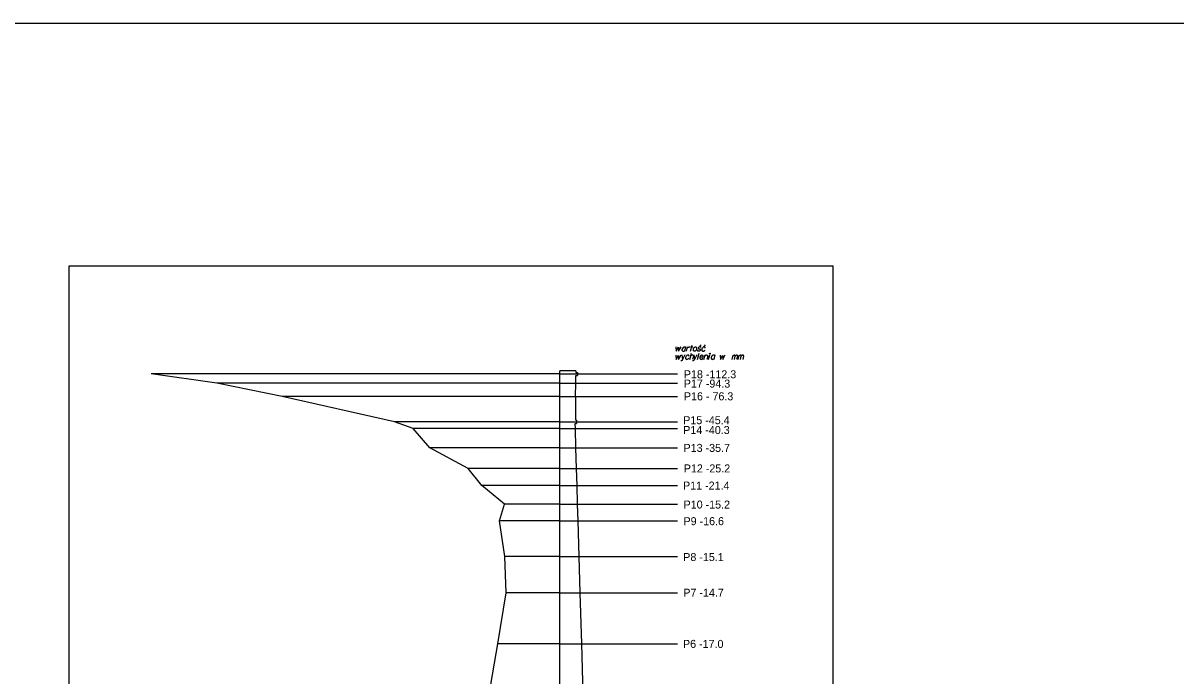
# Model space of a CAD drawing. Extents: x 138 to 6653, y -177 to 1520.
# Drawn here: x 195.15 to 226.83, y 20.71 to 38.66 of the extents above; entities that cross this region are included whole.
import ezdxf

# ---------------------------------------------------------------- set-up
doc = ezdxf.new("R2010")
doc.units = 0
for name, color, linetype in [('15 listopad 2008', 7, 'Continuous'), ('Ramka do drukowania', 7, 'Continuous'), ('Standart wykresów', 7, 'Continuous'), ('Wykresy 4 maj 2008', 7, 'Continuous')]:
    doc.layers.add(name, color=color, linetype=linetype)

msp = doc.modelspace()

# ---------------------------------------------------------------- linework, layer by layer
at = {"layer": '15 listopad 2008'}
msp.add_lwpolyline([(137.936, 38.661), (264.389, 38.661), (264.389, -75.347), (137.936, -75.347)], close=True, dxfattribs=at)
msp.add_lwpolyline([(209.897, 13.297), (209.107, 14.742), (208.657, 16.118), (208.377, 17.485), (208.277, 18.843), (207.957, 20.202), (208.197, 21.593), (208.427, 22.995), (208.387, 23.989), (208.237, 24.969), (208.377, 25.428), (207.757, 25.945), (207.377, 26.413), (206.327, 26.981), (205.867, 27.507), (205.357, 27.694), (202.267, 28.392), (200.467, 28.755), (198.667, 29.011)], dxfattribs=at)
at = {"layer": 'Ramka do drukowania'}
for p, q in [((196.41, 2.285), (196.41, 31.985)), ((196.41, 31.985), (217.41, 31.985)), ((217.41, 2.285), (217.41, 31.985))]:
    msp.add_line(p, q, dxfattribs=at)
at = {"layer": 'Standart wykresów'}
for p, q in [((210.343, 29.095), (209.897, 29.095)), ((209.897, 9.011), (209.897, 29.095)), ((209.897, 29.011), (213.134, 29.011)), ((210.343, 29.095), (210.343, 29.053)), ((210.343, 29.053), (210.38, 29.053)), ((210.343, 28.969), (210.38, 28.969)), ((210.343, 28.755), (210.343, 28.969)), ((210.38, 29.053), (210.38, 29.011)), ((210.38, 29.011), (210.38, 28.969)), ((209.897, 28.755), (213.134, 28.755)), ((210.328, 28.392), (210.343, 28.755)), ((209.897, 28.392), (213.134, 28.392)), ((210.328, 28.392), (210.328, 27.738)), ((209.897, 27.694), (213.134, 27.694)), ((210.328, 27.507), (210.324, 27.65)), ((210.324, 27.65), (210.358, 27.65)), ((210.358, 27.738), (210.328, 27.738)), ((210.358, 27.738), (210.358, 27.694)), ((210.358, 27.694), (210.358, 27.65)), ((209.897, 27.507), (213.134, 27.507)), ((210.343, 26.981), (210.328, 27.507)), ((209.897, 26.981), (213.134, 26.981)), ((210.358, 26.413), (210.343, 26.981)), ((209.897, 26.413), (213.134, 26.413)), ((210.373, 25.945), (210.358, 26.413)), ((209.897, 25.945), (213.134, 25.945)), ((210.385, 25.428), (210.373, 25.945)), ((209.897, 25.428), (213.134, 25.428)), ((210.402, 24.969), (210.385, 25.428)), ((209.897, 24.969), (213.134, 24.969)), ((210.43, 23.989), (210.402, 24.969)), ((209.897, 23.989), (213.134, 23.989)), ((210.46, 22.995), (210.43, 23.989)), ((209.897, 22.995), (213.134, 22.995)), ((210.5, 21.593), (210.46, 22.995)), ((209.897, 21.593), (213.134, 21.593)), ((210.544, 20.202), (210.5, 21.593))]:
    msp.add_line(p, q, dxfattribs=at)
for points in [[(213.492, 29.635), (213.535, 29.801)], [(213.78, 29.813), (213.747, 29.776)], [(213.896, 29.812), (213.864, 29.775)], [(213.088, 29.532), (213.098, 29.412), (213.161, 29.521), (213.162, 29.412), (213.232, 29.534)], [(213.089, 29.754), (213.099, 29.635), (213.162, 29.744), (213.164, 29.635), (213.233, 29.757)], [(213.338, 29.534), (213.271, 29.412), (213.25, 29.377), (213.245, 29.374), (213.238, 29.372), (213.225, 29.369), (213.22, 29.369)], [(213.254, 29.533), (213.271, 29.412)], [(213.353, 29.745), (213.344, 29.751), (213.322, 29.751), (213.309, 29.749), (213.285, 29.736), (213.266, 29.712), (213.256, 29.687), (213.255, 29.674), (213.256, 29.664), (213.26, 29.655), (213.268, 29.644), (213.277, 29.638), (213.292, 29.635), (213.302, 29.636), (213.313, 29.638), (213.327, 29.645)], [(213.356, 29.755), (213.324, 29.635)], [(213.449, 29.498), (213.448, 29.513), (213.441, 29.524), (213.433, 29.529), (213.418, 29.532), (213.403, 29.532), (213.385, 29.52), (213.37, 29.5), (213.36, 29.48), (213.356, 29.466), (213.356, 29.444), (213.357, 29.436), (213.363, 29.426), (213.374, 29.415), (213.387, 29.412), (213.402, 29.414), (213.41, 29.416), (213.427, 29.428), (213.44, 29.45)], [(213.378, 29.635), (213.411, 29.759)], [(213.403, 29.729), (213.41, 29.734), (213.424, 29.745), (213.44, 29.751), (213.451, 29.755), (213.47, 29.759)], [(213.471, 29.412), (213.514, 29.579)], [(213.492, 29.755), (213.555, 29.755)], [(213.496, 29.508), (213.5, 29.513), (213.505, 29.521), (213.509, 29.525), (213.512, 29.528), (213.516, 29.53), (213.52, 29.532), (213.523, 29.533), (213.527, 29.534), (213.537, 29.534), (213.543, 29.533), (213.551, 29.53), (213.556, 29.528), (213.56, 29.524), (213.564, 29.518), (213.567, 29.515), (213.568, 29.512), (213.571, 29.507), (213.571, 29.503), (213.546, 29.412)], [(213.665, 29.534), (213.598, 29.412), (213.577, 29.377), (213.572, 29.374), (213.565, 29.372), (213.552, 29.369), (213.547, 29.369)], [(213.624, 29.755), (213.633, 29.755), (213.644, 29.75), (213.654, 29.736), (213.655, 29.729), (213.657, 29.723), (213.657, 29.717), (213.657, 29.698), (213.653, 29.685), (213.646, 29.669), (213.638, 29.656), (213.625, 29.644), (213.614, 29.635), (213.594, 29.635), (213.586, 29.638), (213.578, 29.644), (213.574, 29.651), (213.569, 29.666), (213.569, 29.69), (213.572, 29.698), (213.577, 29.715), (213.582, 29.724), (213.585, 29.729), (213.598, 29.744), (213.611, 29.751), (213.624, 29.755)], [(213.581, 29.533), (213.598, 29.412)], [(213.78, 29.736), (213.776, 29.745), (213.767, 29.751), (213.759, 29.754), (213.747, 29.755), (213.737, 29.754), (213.721, 29.746), (213.71, 29.736), (213.707, 29.727), (213.705, 29.716), (213.708, 29.71), (213.713, 29.706), (213.716, 29.704), (213.724, 29.702), (213.733, 29.7), (213.746, 29.698), (213.754, 29.695), (213.76, 29.687), (213.763, 29.678), (213.761, 29.666), (213.756, 29.656), (213.746, 29.644), (213.737, 29.639), (213.726, 29.636), (213.713, 29.635), (213.697, 29.636), (213.687, 29.642), (213.682, 29.648), (213.679, 29.657), (213.679, 29.666), (213.683, 29.674)], [(213.683, 29.412), (213.726, 29.579)], [(213.752, 29.482), (213.836, 29.482), (213.838, 29.495), (213.835, 29.507), (213.83, 29.518), (213.814, 29.53), (213.801, 29.532), (213.79, 29.529), (213.776, 29.521), (213.767, 29.512), (213.759, 29.498), (213.754, 29.487), (213.749, 29.465), (213.749, 29.45), (213.75, 29.439), (213.754, 29.428), (213.769, 29.414), (213.78, 29.412), (213.79, 29.414), (213.792, 29.414), (213.809, 29.422), (213.818, 29.431), (213.822, 29.437), (213.823, 29.439), (213.83, 29.45)], [(213.895, 29.72), (213.894, 29.736), (213.887, 29.746), (213.879, 29.751), (213.864, 29.754), (213.849, 29.754), (213.831, 29.742), (213.816, 29.723), (213.806, 29.703), (213.802, 29.689), (213.802, 29.666), (213.803, 29.659), (213.809, 29.648), (213.82, 29.638), (213.833, 29.635), (213.848, 29.636), (213.856, 29.639), (213.873, 29.651), (213.886, 29.673)], [(213.86, 29.412), (213.892, 29.533)], [(213.885, 29.504), (213.889, 29.511), (213.894, 29.518), (213.898, 29.522), (213.903, 29.528), (213.908, 29.53), (213.915, 29.533), (213.921, 29.534), (213.926, 29.534), (213.933, 29.533), (213.938, 29.53), (213.943, 29.528), (213.949, 29.524), (213.954, 29.518), (213.957, 29.515), (213.959, 29.509), (213.962, 29.503), (213.938, 29.412)], [(213.984, 29.412), (214.018, 29.539)], [(214.021, 29.579), (214.027, 29.579), (214.031, 29.576), (214.035, 29.571), (214.035, 29.564), (214.031, 29.559), (214.027, 29.556), (214.021, 29.556), (214.017, 29.559), (214.013, 29.564), (214.013, 29.571), (214.017, 29.576), (214.021, 29.579)], [(214.155, 29.522), (214.146, 29.529), (214.124, 29.529), (214.111, 29.526), (214.087, 29.513), (214.068, 29.49), (214.059, 29.465), (214.057, 29.452), (214.059, 29.441), (214.063, 29.432), (214.07, 29.422), (214.08, 29.415), (214.094, 29.412), (214.104, 29.414), (214.115, 29.415), (214.129, 29.423)], [(214.158, 29.533), (214.127, 29.412)], [(214.303, 29.532), (214.314, 29.412), (214.377, 29.521), (214.378, 29.412), (214.447, 29.534)], [(214.636, 29.412), (214.666, 29.532)], [(214.658, 29.5), (214.664, 29.515), (214.671, 29.522), (214.679, 29.528), (214.687, 29.532), (214.692, 29.534), (214.7, 29.534), (214.702, 29.533), (214.708, 29.528), (214.713, 29.521), (214.717, 29.509), (214.718, 29.503), (214.725, 29.515), (214.732, 29.522), (214.74, 29.528), (214.748, 29.532), (214.755, 29.534), (214.761, 29.534), (214.766, 29.533), (214.77, 29.528), (214.774, 29.521), (214.778, 29.509), (214.78, 29.503), (214.757, 29.412)], [(214.696, 29.412), (214.718, 29.503)], [(214.802, 29.412), (214.832, 29.532)], [(214.824, 29.5), (214.831, 29.515), (214.837, 29.522), (214.845, 29.528), (214.853, 29.532), (214.858, 29.534), (214.866, 29.534), (214.869, 29.533), (214.874, 29.528), (214.879, 29.521), (214.883, 29.509), (214.884, 29.503), (214.891, 29.515), (214.899, 29.522), (214.906, 29.528), (214.914, 29.532), (214.921, 29.534), (214.927, 29.534), (214.933, 29.533), (214.937, 29.528), (214.941, 29.521), (214.944, 29.509), (214.946, 29.503), (214.924, 29.412)], [(214.862, 29.412), (214.884, 29.503)]]:
    msp.add_lwpolyline(points, dxfattribs=at)
at = {"layer": 'Wykresy 4 maj 2008'}
for p, q in [((209.897, 29.011), (198.667, 29.011)), ((209.897, 28.755), (200.467, 28.755)), ((209.897, 28.392), (202.267, 28.392)), ((209.897, 27.694), (205.357, 27.694)), ((209.897, 27.507), (205.867, 27.507)), ((209.897, 26.981), (206.327, 26.981)), ((209.897, 26.413), (207.377, 26.413)), ((209.897, 25.945), (207.757, 25.945)), ((209.897, 25.428), (208.377, 25.428)), ((209.897, 24.969), (208.237, 24.969)), ((209.897, 23.989), (208.387, 23.989)), ((209.897, 22.995), (208.427, 22.995)), ((209.897, 21.593), (208.197, 21.593))]:
    msp.add_line(p, q, dxfattribs=at)

# ---------------------------------------------------------------- texts
for s, p in [('P18 -112.3', (213.307, 28.892)), ('P17 -94.3', (213.306, 28.636)), ('P16 - 76.3', (213.309, 28.287)), ('P15 -45.4', (213.29, 27.63)), ('P14 -40.3', (213.291, 27.36)), ('P13 -35.7', (213.299, 26.868)), ('P12 -25.2', (213.305, 26.304)), ('P11 -21.4', (213.285, 25.832)), ('P10 -15.2', (213.3, 25.31)), ('P9 -16.6', (213.298, 24.853)), ('P8 -15.1', (213.291, 23.866)), ('P7 -14.7', (213.293, 22.887)), ('P6 -17.0', (213.284, 21.478))]:
    msp.add_text(s, height=0.22, dxfattribs=at).set_placement(p)

doc.saveas('drawing.dxf')
